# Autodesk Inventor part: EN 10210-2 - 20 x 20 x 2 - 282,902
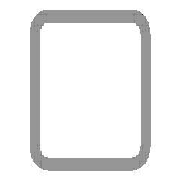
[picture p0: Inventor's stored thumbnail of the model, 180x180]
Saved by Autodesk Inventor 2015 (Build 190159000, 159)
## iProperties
_CCFamilyMember: 1
_CCFamilyDisplayName: DIN EN 10210-2 (Square) - Tube
_FrameMemberDoc: Frame Member File
_Version: 15.0.0
_GetPNFromCC: 1
Created: 2015-05
Part Number: EN 10210-2 - 20 x 20 x 2 - 282,902
Material: Steel, Mild
Description: Tube
Document SubType Name: Modeling
Standard: DIN
Designer: TREINA6
Standard Revision: 1997
Standards Organization: DIN
Language: en-US
Size Designation: 20 x 20 x 2
Categories: <MemberInstance><Categories><Category DisplayName="Structural Shapes" InternalName="089c4875-fa83-4c05-b084-43b9cc11f5ed" Mnemonic="GRDR"><CategoryParameter Dis
Stock Number: 20 x 20 x 2
Density: 7.85 g/cm^3
Appearance: Semi-Polished
IsCustomPart: 1
G_L: 282,902 mm
G_W: 20,000 mm
G_H: 20,000 mm
+FA3F2EE0-632E-44FE-9EA9-D751984C1BD8+CUTDETAIL1: Miter 60,00 deg
+AD2DC2CC-9517-46C6-A196-09C6F70E40CF+CUTDETAIL2: Miter 60,00 deg
Author: TREINA6
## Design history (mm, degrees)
node "Start plane"
node "End plane"
sketch "Sketch"
  geometry: L1 (-10, -7)-(-10, 7); L2 (-7, 10)-(7, 10); L3 (10, 7)-(10, -7); L4 (7, -10)-(-7, -10); L5 (-7, 8)-(7, 8); L6 (8, 7)-(8, -7); L7 (7, -8)-(-7, -8); L8 (-8, -7)-(-8, 7); L9 (0, 14.87)-(0, -14.87) reference; L10 (-14.87, 0)-(14.87, 0) reference; A1 r 3 centre (-7, -7) between (-10, -7) and (-7, -10); A2 r 3 centre (-7, 7) between (-7, 10) and (-10, 7); A3 r 3 centre (7, 7) between (10, 7) and (7, 10); A4 r 3 centre (7, -7) between (7, -10) and (10, -7); A5 r 1 centre (-7, 7) between (-7, 8) and (-8, 7); A6 r 1 centre (7, 7) between (8, 7) and (7, 8); A7 r 1 centre (7, -7) between (7, -8) and (8, -7); A8 r 1 centre (-7, -7) between (-8, -7) and (-7, -8)
  constraints: 16 end point, 16 point on circle, 8 centre point, 8 tangent, 4 parallel, 3 equal radius, 2 perpendicular, 7 other
  dimensions: "d7" = 3 radius of A1 (= G_IR); "d10" = 20 distance between parallel lines of L2 L4 (= G_H); "d11" = 20 distance between parallel lines of L1 L3 (= G_W); "d12" = 2 distance between parallel lines of L3 L6 (= G_T); "d15" = 10 distance between parallel lines of L2 L10 (= 0.5 x d10); "d16" = 10 distance between parallel lines of L9 L3 (= 0.5 x d11)
extrude "Body" new body sketch "Sketch" stored distance "d3" = 282.90163 (= G_L); taper "d4" = 0 deg
node "Driven Length"
  sketch "Sketch3"
    geometry: L1 (0, 0)-(10, 0) reference
    constraints: 2 end point, 1 horizontal
  workplane "Work Plane3"
  sketch "Sketch4"
    geometry: L1 (-2, 0)-(12, 0) reference; L2 (-2, 282.902)-(12, 282.902) reference
    dimensions: "d18" = 282.90163 distance between parallel lines of L1 L2 (derived)
workplane "Work Plane4"
split "Split1"
workplane "Work Plane5"
split "Split2"
body "Solid1"
other parameters: "G_W" = 20 [user parameter; used in 1 equation term], "G_H" = 20 [user parameter; used in 1 equation term], "G_T" = 2 [user parameter; used in 1 equation term], "G_IR" = 3 [user parameter; used in 1 equation term], "G_L" = 282.90163 (= d18) [user parameter; used in 1 equation term], "G_OFFSET_START" = 0 [user parameter; used in 1 equation term], "G_OFFSET_END" = 0 [user parameter; used in 1 equation term], "d13" = 0 (computed from G_OFFSET_START), "d14" = 282.90163 (= G_OFFSET_END + B_L), "B_L" = 282.90163 [user parameter; used in 1 equation term], "d17" = 90 deg
